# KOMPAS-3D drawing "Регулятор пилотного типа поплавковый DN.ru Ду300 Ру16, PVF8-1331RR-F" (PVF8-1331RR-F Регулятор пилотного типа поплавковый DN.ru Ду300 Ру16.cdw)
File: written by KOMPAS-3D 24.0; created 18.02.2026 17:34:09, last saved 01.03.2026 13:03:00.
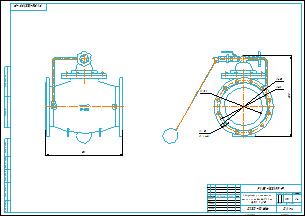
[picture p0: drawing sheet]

Document properties: art: D230-10616; Автор: R2D2; Форматы листов документа: A2; Полное имя файла: PVF8-1331RR-F Регулятор пилотного типа поплавковый DN.ru Ду250 Ру16.m3d; Масса: 130; Наименование: Регулятор пилотного типа поплавковый DN.ru Ду300 Ру16; Количество листов документа: 1; Примечание: D230-10616

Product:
- Part/product: Регулятор пилотного типа поплавковый DN.ru Ду300 Ру16  | designation PVF8-1331RR-F
    Масса: 130
    Раздел спецификации: Прочие изделия
    Примечание: D230-10616
    additional columns: D230-10616

Views: Вид 1, Справа, Проекционный вид 2
Referenced files in E:\Работа\Зайцев\PVF8-1331RR-F Регулятор пилотного типа поплавковый DN.ru Ду15-300\DN300\: PVF8-1331RR-F Регулятор пилотного типа поплавковый DN.ru Ду250 Ру16.m3d
Referenced files in E:\Работа\Зайцев\Для компаса\: чертеж DN.ru А3.cdt
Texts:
  PVF8-1331RR-F
  чертеж DN.ru А3.cdt
  Регулятор пилотного
  типа поплавковый DN.ru
  Ду300 Ру16
  prop
  Регулятор пилотного типа поплавковый DN.ru Ду300 Ру16
  PVF8-1331RR-F Регулятор пилотного типа поплавковый DN.ru Ду300 Ру16
Dimensions and other numbers on the sheet: 0; 3; 2; 4; 600; 460; 410; 300; 26; 12 отв.; 635; 1:4; 1; 130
